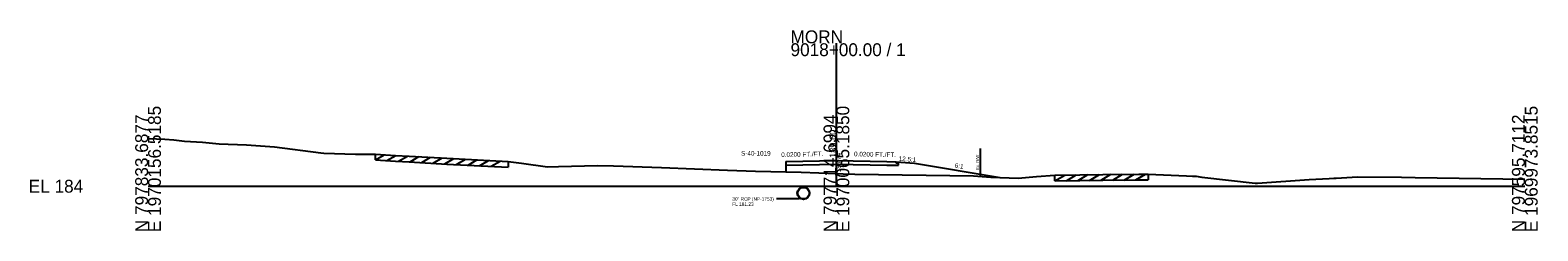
# Model space of a CAD drawing. Extents: x -26 to 2313, y -1511 to 5559.
# Drawn here: x 974.3 to 1302.8, y 3490.3 to 3533.9 of the extents above; entities that cross this region are included whole.
import ezdxf

# ---------------------------------------------------------------- set-up
doc = ezdxf.new("R2010")
doc.units = 0
for name, color, linetype in [('RD_GPK_XS_Cell', 7, 'Continuous'), ('RD_XS_Base', 7, 'Continuous'), ('RD_XS_EarthShd', 7, 'Continuous'), ('RD_XS_ExGround', 7, 'Continuous'), ('RD_XS_ExPaveRet', 7, 'Continuous'), ('RD_XS_ExRW', 7, 'Continuous'), ('RD_XS_Misc_Line', 7, 'Continuous'), ('RD_XS_Pave', 7, 'Continuous'), ('RD_XS_PaveShd', 7, 'Continuous'), ('RD_XS_Pipe', 7, 'Continuous'), ('RD_XS_TieSlope', 7, 'Continuous'), ('RD_XS_TX_Elev_EX', 7, 'Continuous'), ('RD_XS_TX_Elev_PR', 7, 'Continuous'), ('RD_XS_TX_ShdSlope', 7, 'Continuous'), ('RD_XS_TX_Slope', 7, 'Continuous')]:
    doc.layers.add(name, color=color, linetype=linetype)

msp = doc.modelspace()

# ---------------------------------------------------------------- linework, layer by layer
at = {"layer": 'RD_GPK_XS_Cell'}
for p, q in [((1150, 3500), (1150, 3531.09)), ((1000, 3500), (1150, 3500)), ((1150, 3500), (1300, 3500))]:
    msp.add_line(p, q, dxfattribs=at)
at = {"layer": 'RD_XS_Base'}
for p, q in [((1161, 3504.6), (1163.5, 3504.55)), ((1163, 3505.04), (1163, 3505.34)), ((1163.5, 3505.03), (1163, 3505.04)), ((1163.5, 3504.55), (1163.5, 3505.03))]:
    msp.add_line(p, q, dxfattribs=at)
at = {"layer": 'RD_XS_EarthShd'}
msp.add_line((1163, 3505.34), (1167, 3505.02), dxfattribs=at)
at = {"layer": 'RD_XS_ExGround'}
msp.add_lwpolyline([(1000, 3510.36), (1003.64, 3510.21), (1005.6, 3510.09), (1007.94, 3509.81), (1011.83, 3509.61), (1015.49, 3509.25), (1021.44, 3508.99), (1027.54, 3508.57), (1037.68, 3507.25), (1038.33, 3507.17), (1045.17, 3507), (1049.53, 3506.97), (1053.92, 3506.71), (1056.93, 3506.55), (1065.13, 3506.08), (1078.48, 3505.39), (1081.35, 3505), (1087.02, 3504.23), (1089.44, 3504.32), (1097.97, 3504.54), (1101.39, 3504.42), (1111.91, 3504.06), (1126.23, 3503.52), (1132.38, 3503.29), (1142.28, 3503.09), (1150, 3502.74), (1151.48, 3502.68), (1154.02, 3502.62), (1179.88, 3502.27), (1183.61, 3501.99), (1189.59, 3501.75), (1193.61, 3502.11), (1197.59, 3502.41), (1203.07, 3502.5), (1208.04, 3502.58), (1215.86, 3502.62), (1217.93, 3502.63), (1226.26, 3502.25), (1227.62, 3502.17), (1228.37, 3502.16), (1229.65, 3501.99), (1241.25, 3500.65), (1241.73, 3500.68), (1253.01, 3501.45), (1257.39, 3501.71), (1258.36, 3501.76), (1258.86, 3501.78), (1263.57, 3502.03), (1273.1, 3501.98), (1276.13, 3501.92), (1300, 3501.53)], dxfattribs=at)
at = {"layer": 'RD_XS_ExPaveRet'}
for p, q in [((1049.53, 3505.72), (1049.53, 3506.97)), ((1049.53, 3505.72), (1053.92, 3505.46)), ((1053.92, 3505.46), (1056.93, 3505.3)), ((1056.93, 3505.3), (1065.13, 3504.83)), ((1065.13, 3504.83), (1078.48, 3504.14)), ((1078.48, 3505.39), (1078.48, 3504.14)), ((1197.59, 3501.16), (1197.59, 3502.41)), ((1217.93, 3502.63), (1217.93, 3501.38)), ((1197.59, 3501.16), (1203.07, 3501.25)), ((1203.07, 3501.25), (1208.04, 3501.33)), ((1208.04, 3501.33), (1215.86, 3501.37)), ((1215.86, 3501.37), (1217.93, 3501.38))]:
    msp.add_line(p, q, dxfattribs=at)
at = {"layer": 'RD_XS_ExRW'}
msp.add_line((1181.33, 3508.17), (1181.33, 3502.17), dxfattribs=at)
at = {"layer": 'RD_XS_Misc_Line'}
for p, q in [((1049.53, 3505.72), (1051.44, 3506.86)), ((1052.06, 3505.57), (1053.97, 3506.71)), ((1054.58, 3505.43), (1056.51, 3506.57)), ((1057.11, 3505.29), (1059.03, 3506.43)), ((1059.63, 3505.15), (1061.55, 3506.29)), ((1062.15, 3505), (1064.07, 3506.14)), ((1064.68, 3504.86), (1066.61, 3506.01)), ((1067.2, 3504.73), (1069.14, 3505.88)), ((1069.73, 3504.59), (1071.66, 3505.74)), ((1072.25, 3504.46), (1074.19, 3505.61)), ((1074.78, 3504.33), (1076.71, 3505.48)), ((1197.59, 3501.16), (1199.75, 3502.44)), ((1200.11, 3501.2), (1202.27, 3502.48)), ((1202.64, 3501.24), (1204.8, 3502.52)), ((1205.16, 3501.28), (1207.32, 3502.57)), ((1207.69, 3501.32), (1209.82, 3502.59)), ((1210.21, 3501.34), (1212.33, 3502.6)), ((1212.73, 3501.35), (1214.86, 3502.61)), ((1215.26, 3501.37), (1217.38, 3502.63))]:
    msp.add_line(p, q, dxfattribs=at)
at = {"layer": 'RD_XS_Pave'}
for p, q in [((1139, 3505.38), (1150, 3505.6)), ((1150, 3505.6), (1161, 3505.38)), ((1139, 3505.38), (1139, 3503.15)), ((1139, 3504.6), (1150, 3504.82)), ((1150, 3504.82), (1161, 3504.6))]:
    msp.add_line(p, q, dxfattribs=at)
at = {"layer": 'RD_XS_PaveShd'}
msp.add_line((1161, 3505.38), (1163, 3505.34), dxfattribs=at)
at = {"layer": 'RD_XS_Pipe'}
msp.add_line((1141.97, 3497.23), (1136.97, 3497.23), dxfattribs=at)
for radius in [1.35, 1.25]:
    msp.add_circle((1142.81, 3498.48), radius, dxfattribs=at)
at = {"layer": 'RD_XS_TieSlope'}
msp.add_line((1167, 3505.02), (1185.67, 3501.91), dxfattribs=at)

# ---------------------------------------------------------------- texts
at = {"layer": 'RD_GPK_XS_Cell'}
for s, p in [('MORN', (1140, 3531.09)), ('9018+00.00 / 1', (1140, 3528.29)), ('EL 184', (974, 3498.6))]:
    msp.add_text(s, height=2.8, dxfattribs=at).set_placement(p)
for s, p in [('N 797833.6877', (1000, 3490)), ('E 1970156.5185', (1002.8, 3490)), ('N 797714.6994', (1150, 3490)), ('E 1970065.1850', (1152.8, 3490)), ('N 797595.7112', (1300, 3490)), ('E 1969973.8515', (1302.8, 3490))]:
    msp.add_text(s, height=2.8, rotation=90, dxfattribs=at).set_placement(p)
at = {"layer": 'RD_XS_ExRW'}
msp.add_text('Ex. R/W ', height=0.65, rotation=90, dxfattribs=at).set_placement((1181.08, 3503.55))
at = {"layer": 'RD_XS_Pipe'}
for s, p in [('30" RCP (NP-1753)', (1127.3, 3496.85)), ('FL 181.23', (1127.3, 3495.73))]:
    msp.add_text(s, height=0.75, dxfattribs=at).set_placement(p)
at = {"layer": 'RD_XS_TX_Elev_EX'}
msp.add_text('186.74', height=1, rotation=90, dxfattribs=at).set_placement((1150.98, 3503.03))
at = {"layer": 'RD_XS_TX_Elev_PR'}
msp.add_text(' 189.60', height=1.5, rotation=90, dxfattribs=at).set_placement((1150, 3505.6))
at = {"layer": 'RD_XS_TX_ShdSlope'}
msp.add_text('12.5:1', height=1, rotation=355.4261, dxfattribs=at).set_placement((1163.54, 3505.55))
at = {"layer": 'RD_XS_TX_Slope'}
msp.add_text('S-40-1019', height=1, dxfattribs=at).set_placement((1129.22, 3506.65))
for s, rotation, p in [('0.0200 FT./FT.', 1.1458, (1137.98, 3506.36)), ('0.0200 FT./FT.', 358.8542, (1153.83, 3506.52)), ('6:1', 350.5377, (1175.72, 3504.07))]:
    msp.add_text(s, height=1, rotation=rotation, dxfattribs=at).set_placement(p)

doc.saveas('drawing.dxf')
